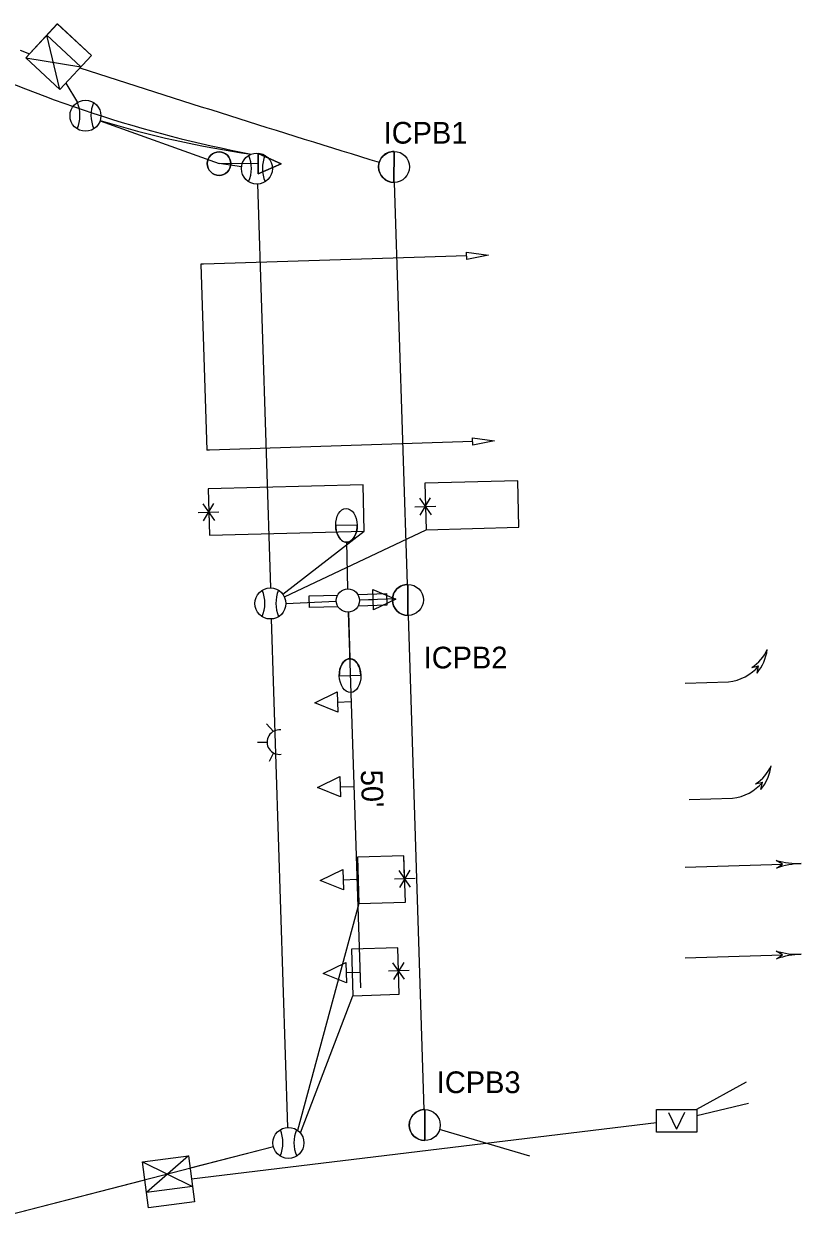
# Model space of a CAD drawing. Extents: x 596176 to 605330, y 332416 to 402398.
# Drawn here: x 604089.1 to 604189.5, y 339281.5 to 339435.3 of the extents above; entities that cross this region are included whole.
import ezdxf

# ---------------------------------------------------------------- set-up
doc = ezdxf.new("R2010")
doc.units = 0
for name, color, linetype in [('P_LTG', 7, 'Continuous'), ('P_SIG', 7, 'Continuous'), ('P_SIG_Bold', 7, 'Continuous'), ('P_SIG_Conduit', 7, 'Continuous'), ('P_SIG_IC', 7, 'Continuous'), ('P_SIG_Loops', 7, 'Continuous'), ('P_SIG_Text', 7, 'Continuous')]:
    doc.layers.add(name, color=color, linetype=linetype)

# ---------------------------------------------------------------- blocks, each defined once
blk = doc.blocks.new('CONTROL CABINET')
at = {"layer": 'P_SIG'}
for p, q in [((-0.229, 0.305), (0.229, 0.305)), ((-0.229, -0.152), (-0.229, 0.305)), ((0.229, 0.305), (0.229, -0.152)), ((-0.229, 0.152), (0.229, 0.152)), ((-0.229, -0.152), (0.229, 0.152)), ((0.229, -0.152), (-0.229, 0.152)), ((0.229, -0.152), (-0.229, -0.152))]:
    blk.add_line(p, q, dxfattribs=at)
blk = doc.blocks.new('_U226')
at = {"layer": 'P_SIG'}
blk.add_line((0.03, 6.11), (-0.03, -6.09), dxfattribs=at)
blk.add_lwpolyline([(-0.03, -6.09), (0.03, 6.11)], dxfattribs=at)
blk.add_circle((0, 0.01), 6.1, dxfattribs=at)
for start, end in [(89.7008, 180), (180, 269.7008)]:
    blk.add_arc((0, 0.01), 6.1, start, end, dxfattribs=at)

msp = doc.modelspace()

# ---------------------------------------------------------------- linework, layer by layer
at = {"layer": 'P_LTG'}
for p, q in [((604132.2, 339370.57), (604129.43, 339370.51)), ((604132.2, 339370.57), (604129.43, 339370.51)), ((604130.98, 339362.34), (604130.85, 339368.41)), ((604130.98, 339362.34), (604130.85, 339368.41)), ((604131.06, 339359.34), (604131.23, 339353.34)), ((604131.06, 339359.34), (604131.23, 339353.34)), ((604129.9, 339351.11), (604132.67, 339351.19)), ((604129.9, 339351.11), (604132.67, 339351.19))]:
    msp.add_line(p, q, dxfattribs=at)
for centre, major_axis in [((604130.81, 339370.54), (-0.05, 2.18)), ((604130.81, 339370.54), (-0.05, 2.18)), ((604131.28, 339351.15), (0.06, -2.18)), ((604131.28, 339351.15), (0.06, -2.18))]:
    msp.add_ellipse(centre, major_axis=major_axis, ratio=0.636439, dxfattribs=at)
for centre, major_axis in [((604130.81, 339370.54), (-0.05, 2.18)), ((604130.81, 339370.54), (-0.05, 2.18)), ((604131.28, 339351.15), (0.06, -2.18)), ((604131.28, 339351.15), (0.06, -2.18))]:
    msp.add_ellipse(centre, major_axis=major_axis, ratio=0.636439, start_param=1.570796, end_param=4.712389, dxfattribs=at)
at = {"layer": 'P_SIG'}
for p, q in [((604089.39, 339430.9), (604093.47, 339435.3)), ((604093.47, 339435.3), (604097.87, 339431.21)), ((604092.11, 339433.83), (604096.51, 339429.75)), ((604093.79, 339426.82), (604092.11, 339433.83)), ((604093.79, 339426.82), (604089.39, 339430.9)), ((604089.39, 339430.9), (604096.51, 339429.75)), ((604097.87, 339431.21), (604093.79, 339426.82)), ((604119.42, 339417.24), (604114.36, 339417.25)), ((604119.42, 339417.24), (604114.36, 339417.25)), ((604134.26, 339360.94), (604132.49, 339360.89)), ((604134.26, 339360.94), (604132.49, 339360.89)), ((604183.16, 339352.21), (604184.05, 339352.42)), ((604183.84, 339351.47), (604184.05, 339352.42)), ((604174.58, 339350.18), (604180.17, 339350.35)), ((604129.67, 339347.74), (604131.44, 339347.8)), ((604129.67, 339347.74), (604131.44, 339347.8)), ((604121.38, 339343.95), (604120.48, 339344.93)), ((604121.38, 339343.95), (604120.48, 339344.93)), ((604120.56, 339342.52), (604119.33, 339342.5)), ((604120.56, 339342.52), (604119.33, 339342.5)), ((604121.41, 339341.16), (604120.83, 339340.08)), ((604121.41, 339341.16), (604120.83, 339340.08)), ((604130.02, 339336.8), (604131.79, 339336.85)), ((604130.02, 339336.8), (604131.79, 339336.85)), ((604183.66, 339337.19), (604184.55, 339337.4)), ((604184.34, 339336.46), (604184.55, 339337.4)), ((604175.08, 339335.16), (604180.67, 339335.34)), ((604174.58, 339326.42), (604187.15, 339326.81)), ((604130.4, 339324.8), (604132.17, 339324.86)), ((604130.4, 339324.8), (604132.17, 339324.86)), ((604174.58, 339314.71), (604187.15, 339315.1)), ((604130.77, 339312.81), (604132.54, 339312.86)), ((604130.77, 339312.81), (604132.54, 339312.86)), ((604172.4, 339294.75), (604173.44, 339292.59)), ((604174.48, 339294.75), (604173.44, 339292.59)), ((604104.48, 339288.38), (604110.43, 339289.16)), ((604105.26, 339282.43), (604104.48, 339288.38)), ((604104.48, 339288.38), (604110.95, 339285.2)), ((604110.43, 339289.16), (604105, 339284.42)), ((604110.43, 339289.16), (604111.21, 339283.21)), ((604110.95, 339285.2), (604105, 339284.42)), ((604111.21, 339283.21), (604105.26, 339282.43))]:
    msp.add_line(p, q, dxfattribs=at)
for points in [[(604122.38, 339417.24), (604119.42, 339415.92), (604119.42, 339418.56), (604122.38, 339417.24)], [(604119.42, 339415.92), (604122.38, 339417.24), (604119.42, 339418.56), (604119.42, 339415.92)], [(604122.38, 339417.24), (604119.42, 339415.92), (604119.42, 339418.56), (604122.38, 339417.24)], [(604119.42, 339415.92), (604122.38, 339417.24), (604119.42, 339418.56), (604119.42, 339415.92)], [(604186.36, 339326.29), (604187.15, 339326.81), (604186.33, 339327.28)], [(604186.36, 339314.58), (604187.15, 339315.1), (604186.33, 339315.58)]]:
    msp.add_lwpolyline(points, dxfattribs=at)
for points in [[(604137.21, 339361.03), (604134.29, 339359.62), (604134.22, 339362.26)], [(604137.21, 339361.03), (604134.29, 339359.62), (604134.22, 339362.26)], [(604126.71, 339347.65), (604129.62, 339349.06), (604129.71, 339346.43)], [(604126.71, 339347.65), (604129.62, 339349.06), (604129.71, 339346.43)], [(604127.06, 339336.7), (604129.97, 339338.11), (604130.06, 339335.48)], [(604127.06, 339336.7), (604129.97, 339338.11), (604130.06, 339335.48)], [(604127.44, 339324.71), (604130.36, 339326.12), (604130.44, 339323.49)], [(604127.44, 339324.71), (604130.36, 339326.12), (604130.44, 339323.49)], [(604127.81, 339312.71), (604130.73, 339314.12), (604130.81, 339311.49)], [(604127.81, 339312.71), (604130.73, 339314.12), (604130.81, 339311.49)], [(604170.85, 339295.13), (604176.06, 339295.13), (604176.06, 339292.21), (604170.85, 339292.21)]]:
    msp.add_lwpolyline(points, close=True, dxfattribs=at)
for centre, radius in [((604097.11, 339423.43), 2), ((604114.36, 339417.25), 1.52), ((604114.36, 339417.25), 1.52), ((604114.36, 339417.25), 1.52), ((604114.36, 339417.25), 1.52), ((604114.36, 339417.25), 1.52), ((604114.36, 339417.25), 1.52), ((604119.25, 339416.61), 2), ((604119.25, 339416.61), 2), ((604120.99, 339360.46), 2), ((604120.99, 339360.46), 2), ((604123.32, 339290.82), 2), ((604123.32, 339290.82), 2)]:
    msp.add_circle(centre, radius, dxfattribs=at)
for centre, radius, start, end in [((604092.04, 339423.47), 4.36, 336.6741, 22.5272), ((604102.18, 339423.48), 4.36, 157.5751, 203.4282), ((604114.36, 339417.25), 1.52, 0, 180), ((604114.36, 339417.25), 1.52, 0, 180), ((604114.18, 339416.65), 4.36, 336.6741, 22.5272), ((604114.18, 339416.65), 4.36, 336.6741, 22.5272), ((604124.32, 339416.66), 4.36, 157.5751, 203.4282), ((604124.32, 339416.66), 4.36, 157.5751, 203.4282), ((604114.36, 339417.25), 1.52, 180, 0), ((604114.36, 339417.25), 1.52, 180, 0), ((604115.92, 339360.5), 4.36, 336.6741, 22.5272), ((604115.92, 339360.5), 4.36, 336.6741, 22.5272), ((604126.06, 339360.51), 4.36, 157.5751, 203.4282), ((604126.06, 339360.51), 4.36, 157.5751, 203.4282), ((604180.45, 339356.58), 5.14, 301.8545, 336.5029), ((604179.15, 339355.32), 6.07, 320.5981, 352.4543), ((604179.59, 339356.12), 5.8, 275.7349, 320.2988), ((604122.14, 339342.56), 1.58, 83.3712, 278.8787), ((604122.14, 339342.56), 1.58, 83.3712, 278.8787), ((604180.95, 339341.56), 5.14, 301.8545, 336.5029), ((604179.65, 339340.31), 6.07, 320.5981, 352.4543), ((604180.09, 339341.1), 5.8, 275.7349, 320.2988), ((604189.22, 339337.37), 10.49, 254.0073, 271.7696), ((604189.87, 339316.4), 10.49, 91.7696, 109.5319), ((604189.22, 339325.66), 10.49, 254.0073, 271.7696), ((604189.87, 339304.69), 10.49, 91.7696, 109.5319), ((604118.25, 339290.85), 4.36, 336.6741, 22.5272), ((604118.25, 339290.85), 4.36, 336.6741, 22.5272), ((604128.39, 339290.86), 4.36, 157.5751, 203.4282), ((604128.39, 339290.86), 4.36, 157.5751, 203.4282)]:
    msp.add_arc(centre, radius, start, end, dxfattribs=at)
at = {"layer": 'P_SIG_Bold'}
msp.add_line((604131.05, 339359.34), (604132.61, 339310.86), dxfattribs=at)
msp.add_line((604131.05, 339359.34), (604132.61, 339310.86), dxfattribs=at)
for points in [[(604129.73, 339360.05), (604126.03, 339359.93), (604125.98, 339361.43), (604129.68, 339361.55)], [(604129.73, 339360.05), (604126.03, 339359.93), (604125.98, 339361.43), (604129.68, 339361.55)], [(604132.28, 339361.63), (604135.98, 339361.75), (604136.02, 339360.25), (604132.32, 339360.13)], [(604132.28, 339361.63), (604135.98, 339361.75), (604136.02, 339360.25), (604132.32, 339360.13)]]:
    msp.add_lwpolyline(points, dxfattribs=at)
msp.add_circle((604131, 339360.84), 1.5, dxfattribs=at)
msp.add_circle((604131, 339360.84), 1.5, dxfattribs=at)
at = {"layer": 'P_SIG_Conduit'}
msp.add_line((604123.26, 339292.82), (604121.13, 339358.47), dxfattribs=at)
msp.add_line((604123.26, 339292.82), (604121.13, 339358.47), dxfattribs=at)
for points in [[(604088.69, 339431.88), (604089.89, 339431.44)], [(604094.56, 339427.65), (604096.08, 339425.14)], [(604098.99, 339422.76), (604114.36, 339417.25)], [(604117.26, 339416.83), (604114.36, 339417.25)], [(604119.33, 339414.62), (604121, 339362.46)], [(604119.33, 339414.62), (604121, 339362.46)], [(604122.99, 339360.45), (604129.5, 339360.76)], [(604122.99, 339360.45), (604129.5, 339360.76)], [(604137.13, 339361.04), (604132.5, 339360.89)], [(604137.13, 339361.04), (604132.5, 339360.89)], [(604182.45, 339298.67), (604176.04, 339295.13)], [(604182.73, 339295.92), (604176.06, 339294.31)], [(604110.82, 339286.19), (604170.85, 339293.47)], [(604121.39, 339290.32), (604087.19, 339281.49)], [(604121.39, 339290.32), (604110.65, 339287.54)], [(604104.79, 339286.03), (604087.19, 339281.49)]]:
    msp.add_lwpolyline(points, dxfattribs=at)
for centre, radius, start, end in [((604149.94, 339581.75), 166.28, 244.5471, 259.1012), ((604137.47, 339549.05), 131.96, 253.0559, 261.7336)]:
    msp.add_arc(centre, radius, start, end, dxfattribs=at)
at = {"layer": 'P_SIG_IC'}
for p, q in [((604138.69, 339362.92), (604137.02, 339414.83)), ((604140.86, 339295.11), (604138.81, 339358.92)), ((604154.49, 339289.13), (604142.84, 339292.55))]:
    msp.add_line(p, q, dxfattribs=at)
msp.add_arc((604953.99, 342080.15), 2785.82, 252.07054, 252.90432, dxfattribs=at)
at = {"layer": 'P_SIG_Loops'}
for p, q in [((604112.01, 339404.25), (604112.78, 339380.26)), ((604112.01, 339404.25), (604112.78, 339380.26)), ((604113.8, 339371.19), (604112.32, 339373.33)), ((604113.8, 339371.19), (604112.32, 339373.33)), ((604112.35, 339371.15), (604113.7, 339373.35)), ((604112.35, 339371.15), (604113.7, 339373.35)), ((604139.66, 339372.94), (604142.34, 339373.01)), ((604139.66, 339372.94), (604142.34, 339373.01)), ((604141.79, 339371.92), (604140.31, 339374.05)), ((604141.79, 339371.92), (604140.31, 339374.05)), ((604140.34, 339371.87), (604141.69, 339374.08)), ((604140.34, 339371.87), (604141.69, 339374.08)), ((604111.67, 339372.22), (604114.35, 339372.28)), ((604111.67, 339372.22), (604114.35, 339372.28)), ((604113.04, 339372.27), (604113.12, 339369.27)), ((604113.04, 339372.27), (604113.12, 339369.27)), ((604122.58, 339361.68), (604133.1, 339369.79)), ((604122.58, 339361.68), (604133.1, 339369.79)), ((604122.8, 339361.32), (604141.11, 339369.99)), ((604122.8, 339361.32), (604141.11, 339369.99)), ((604138.33, 339324.9), (604138.23, 339327.9)), ((604138.33, 339324.9), (604138.23, 339327.9)), ((604137.56, 339325.97), (604139.06, 339323.84)), ((604137.56, 339325.97), (604139.06, 339323.84)), ((604139.01, 339326.02), (604137.67, 339323.81)), ((604139.01, 339326.02), (604137.67, 339323.81)), ((604139.7, 339324.96), (604137.02, 339324.87)), ((604139.7, 339324.96), (604137.02, 339324.87)), ((604132.42, 339321.71), (604124.51, 339292.43)), ((604132.42, 339321.71), (604124.51, 339292.43)), ((604137.54, 339313.01), (604137.45, 339316)), ((604137.54, 339313.01), (604137.45, 339316)), ((604138.91, 339313.07), (604136.24, 339312.98)), ((604138.91, 339313.07), (604136.24, 339312.98)), ((604136.77, 339314.08), (604138.27, 339311.95)), ((604136.77, 339314.08), (604138.27, 339311.95)), ((604138.23, 339314.13), (604136.89, 339311.92)), ((604138.23, 339314.13), (604136.89, 339311.92)), ((604124.86, 339292.1), (604131.64, 339309.82)), ((604124.86, 339292.1), (604131.64, 339309.82))]:
    msp.add_line(p, q, dxfattribs=at)
for points in [[(604146.35, 339405.35), (604112.37, 339404.25)], [(604146.35, 339405.35), (604112.37, 339404.25)], [(604112.37, 339404.25), (604112.01, 339404.25)], [(604112.37, 339404.25), (604112.01, 339404.25)], [(604147.12, 339381.36), (604113.14, 339380.26)], [(604147.12, 339381.36), (604113.14, 339380.26)], [(604113.14, 339380.26), (604112.78, 339380.26)], [(604113.14, 339380.26), (604112.78, 339380.26)]]:
    msp.add_lwpolyline(points, dxfattribs=at)
for points in [[(604146.33, 339405.81), (604149.15, 339405.44), (604146.36, 339404.88)], [(604146.33, 339405.81), (604149.15, 339405.44), (604146.36, 339404.88)], [(604147.1, 339381.83), (604149.92, 339381.45), (604147.13, 339380.89)], [(604147.1, 339381.83), (604149.92, 339381.45), (604147.13, 339380.89)], [(604141.11, 339369.99), (604153.1, 339370.3), (604152.95, 339376.3), (604140.95, 339375.99)], [(604141.11, 339369.99), (604153.1, 339370.3), (604152.95, 339376.3), (604140.95, 339375.99)], [(604113.12, 339369.27), (604133.11, 339369.79), (604132.96, 339375.78), (604112.96, 339375.27)], [(604113.12, 339369.27), (604133.11, 339369.79), (604132.96, 339375.78), (604112.96, 339375.27)], [(604138.23, 339327.9), (604132.24, 339327.71), (604132.42, 339321.71), (604138.42, 339321.9)], [(604138.23, 339327.9), (604132.24, 339327.71), (604132.42, 339321.71), (604138.42, 339321.9)], [(604137.45, 339316), (604131.45, 339315.82), (604131.64, 339309.82), (604137.64, 339310.01)], [(604137.45, 339316), (604131.45, 339315.82), (604131.64, 339309.82), (604137.64, 339310.01)]]:
    msp.add_lwpolyline(points, close=True, dxfattribs=at)

# ---------------------------------------------------------------- block references
at = {"layer": 'P_SIG', "xscale": 13.123333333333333, "yscale": 13.123333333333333, "rotation": -43.04627252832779}
msp.add_blockref('CONTROL CABINET', (604092.95, 339430.32), dxfattribs=at)
at = {"layer": 'P_SIG_IC', "xscale": 0.32808333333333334, "yscale": 0.32808333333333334}
for p in [(604136.96, 339416.82), (604138.75, 339360.92), (604140.93, 339293.12)]:
    msp.add_blockref('_U226', p, dxfattribs=at)

# ---------------------------------------------------------------- texts
at = {"layer": 'P_SIG'}
msp.add_text("50'", height=2.8, rotation=271.8373, dxfattribs=at).set_placement((604132.66, 339338.95))
msp.add_text("50'", height=2.8, rotation=271.8373, dxfattribs=at).set_placement((604132.66, 339338.95))
at = {"layer": 'P_SIG_Text'}
for s, p in [('ICPB1', (604135.62, 339419.83)), ('ICPB2', (604140.79, 339352.08)), ('ICPB3', (604142.48, 339297.25))]:
    msp.add_text(s, height=2.8, dxfattribs=at).set_placement(p)

doc.saveas('drawing.dxf')
